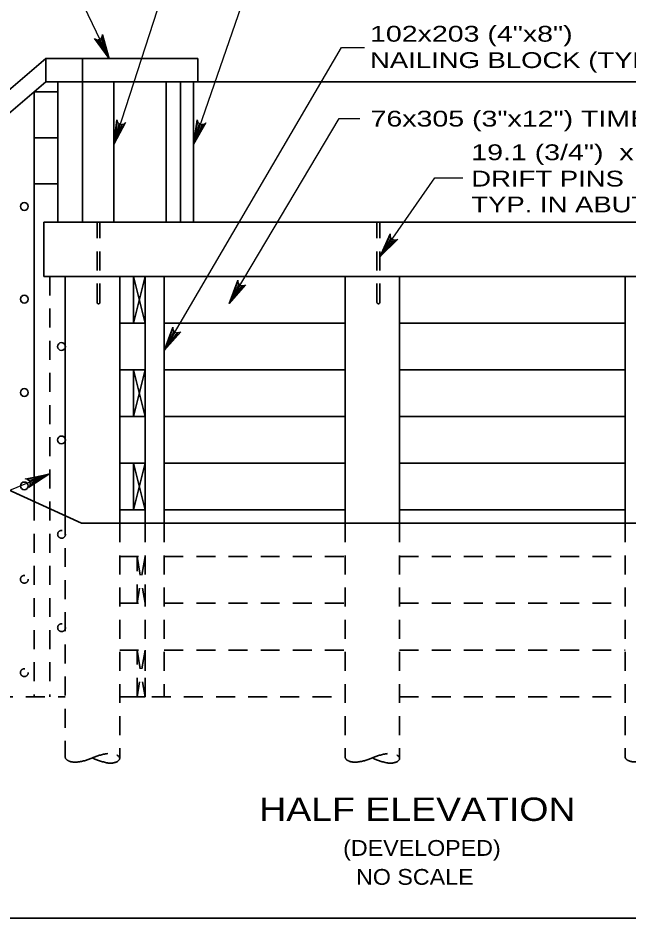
# Model space of a CAD drawing. Extents: x -6.4 to 73.1, y -66 to 0.
# Drawn here: x 7.37 to 12, y -21.25 to -14.42 of the extents above; entities that cross this region are included whole.
import ezdxf
from ezdxf.enums import TextEntityAlignment as Align

# ---------------------------------------------------------------- set-up
doc = ezdxf.new("R2010")
doc.units = 0
doc.header["$LTSCALE"] = 0.048
doc.linetypes.add('MEDIUM_DASHED', pattern=[4.5, 3, -1.5])
for name, color, linetype, lineweight in [('1', 7, 'Continuous', 13), ('4', 7, 'Continuous', 25), ('5', 7, 'Continuous', 25), ('52', 7, 'Continuous', 25)]:
    doc.layers.add(name, color=color, linetype=linetype, lineweight=lineweight)

msp = doc.modelspace()

# ---------------------------------------------------------------- hatches: boundary and pattern name
at = {"layer": '5'}
for points in [[(8.06058, -14.72783), (8.01867, -14.617), (8.00092, -14.62542)], [(8.09567, -15.38017), (8.1415, -15.27092), (8.12283, -15.26483)], [(10.1175, -16.23142), (10.193, -16.14008), (10.17692, -16.12883)], [(8.97192, -16.5865), (9.04092, -16.49008), (9.024, -16.48)], [(8.48033, -16.94342), (8.5485, -16.84642), (8.5315, -16.8365)], [(7.61, -17.87892), (7.497, -17.91467), (7.5045, -17.93292)]]:
    msp.add_hatch(color=256, dxfattribs=at).paths.add_polyline_path(points)

# ---------------------------------------------------------------- linework, layer by layer
at = {"layer": '1', "lineweight": 35}
msp.add_lwpolyline([(1.75, -21.25), (33.25, -21.25), (33.25, -0.75), (1.75, -0.75)], close=True, dxfattribs=at)
at = {"layer": '4', "lineweight": 35}
for p, q in [((7.57942, -14.72783), (5.12433, -16.82092)), ((7.57942, -14.72783), (7.57942, -14.905)), ((8.73492, -14.72783), (7.57942, -14.72783)), ((7.85875, -14.72783), (7.85875, -14.905)), ((8.73492, -14.72783), (8.73492, -14.905)), ((7.57942, -14.905), (5.12433, -16.99808)), ((8.41083, -14.905), (7.57942, -14.905)), ((7.67092, -14.905), (7.67092, -15.968)), ((7.85875, -14.905), (7.85875, -15.968)), ((8.09567, -14.905), (8.09567, -15.968)), ((8.41083, -14.905), (13.83458, -14.905)), ((8.49383, -14.905), (8.49383, -15.968)), ((8.60392, -14.905), (8.60392, -15.968)), ((8.70217, -14.905), (8.70217, -15.968)), ((7.49133, -14.98008), (7.49133, -18.08933)), ((7.49133, -14.98008), (7.63358, -14.98008)), ((7.63358, -14.97908), (7.67092, -14.97908)), ((7.49133, -15.32842), (7.67092, -15.32842)), ((7.49133, -15.67775), (7.67092, -15.67775)), ((7.56575, -15.968), (7.56575, -16.38133)), ((7.56575, -15.968), (13.83458, -15.968)), ((7.56575, -16.38133), (13.83458, -16.38133)), ((7.72817, -16.38133), (7.72817, -18.19792)), ((8.14133, -16.38133), (8.14133, -18.25408)), ((8.24625, -16.38133), (8.24625, -16.73567)), ((8.24625, -16.73567), (8.33483, -16.38133)), ((8.33483, -16.38133), (8.33483, -18.25408)), ((8.48033, -16.38133), (8.48033, -18.25408)), ((9.85417, -16.38133), (9.85417, -18.25408)), ((10.26733, -16.38133), (10.26733, -18.25408)), ((11.98008, -16.38133), (11.98008, -18.25408)), ((8.14133, -16.73567), (8.33483, -16.73567)), ((8.48033, -16.73567), (9.85417, -16.73567)), ((10.26733, -16.73567), (11.98008, -16.73567)), ((5.33375, -17.09975), (7.8505, -18.25408)), ((8.14133, -17.09), (8.33483, -17.09)), ((8.24625, -17.44433), (8.33483, -17.09)), ((8.33483, -17.44433), (8.24625, -17.09)), ((8.24625, -17.09), (8.24625, -17.44433)), ((8.33483, -17.09), (8.33483, -17.44433)), ((8.48033, -17.09), (9.85417, -17.09)), ((10.26733, -17.09), (11.98008, -17.09)), ((8.14133, -17.44433), (8.33483, -17.44433)), ((8.48033, -17.44433), (9.85417, -17.44433)), ((10.26733, -17.44433), (11.98008, -17.44433)), ((8.14133, -17.79867), (8.33483, -17.79867)), ((8.24625, -17.79867), (8.24625, -18.153)), ((8.24625, -18.153), (8.33483, -17.79867)), ((8.48033, -17.79867), (9.85417, -17.79867)), ((10.26733, -17.79867), (11.98008, -17.79867)), ((8.14133, -18.153), (8.33483, -18.153)), ((8.48033, -18.153), (9.85417, -18.153)), ((10.26733, -18.153), (11.98008, -18.153)), ((7.8505, -18.25408), (13.83458, -18.25408))]:
    msp.add_line(p, q, dxfattribs=at)
at = {"layer": '4', "linetype": 'MEDIUM_DASHED', "lineweight": 35}
for p, q in [((7.96933, -16.5785), (7.96933, -15.968)), ((7.9915, -16.5785), (7.9915, -15.968)), ((10.09533, -16.5785), (10.09533, -15.968)), ((10.1175, -16.5785), (10.1175, -15.968)), ((7.61, -16.38133), (7.61, -19.57033)), ((7.49133, -18.08933), (7.49133, -19.57033)), ((7.72817, -18.19792), (7.72817, -20.02908)), ((8.14133, -18.25408), (8.14133, -20.04)), ((8.33483, -18.25408), (8.33483, -19.57033)), ((8.48033, -18.25408), (8.48033, -19.57033)), ((9.85417, -18.25408), (9.85417, -20.02908)), ((10.26733, -18.25408), (10.26733, -20.04)), ((11.98008, -18.25408), (11.98008, -20.02683)), ((8.14133, -18.50733), (8.33483, -18.50733)), ((8.33483, -18.50733), (8.27317, -18.86167)), ((8.27317, -18.86167), (8.27317, -18.50733)), ((8.48033, -18.50733), (9.85417, -18.50733)), ((10.26733, -18.50733), (11.98008, -18.50733)), ((8.14133, -18.86167), (8.33483, -18.86167)), ((8.48033, -18.86167), (9.85417, -18.86167)), ((10.26733, -18.86167), (11.98008, -18.86167)), ((8.14133, -19.216), (8.33483, -19.216)), ((8.27317, -19.57033), (8.27317, -19.216)), ((8.27317, -19.216), (8.33483, -19.57033)), ((8.33483, -19.216), (8.27317, -19.57033)), ((8.33483, -19.57033), (8.33483, -19.216)), ((8.48033, -19.216), (9.85417, -19.216)), ((10.26733, -19.216), (11.98008, -19.216)), ((6.94125, -19.57033), (7.72817, -19.57033)), ((8.14133, -19.57033), (9.85417, -19.57033)), ((8.19092, -19.57033), (8.36808, -19.57033)), ((10.26733, -19.57033), (11.98008, -19.57033))]:
    msp.add_line(p, q, dxfattribs=at)
at = {"layer": '4', "lineweight": 35}
for points in [[(8.33483, -16.38133), (8.33483, -16.73567), (8.24625, -16.38133)], [(8.33483, -17.79867), (8.33483, -18.153), (8.24625, -17.79867)]]:
    msp.add_lwpolyline(points, dxfattribs=at)
at = {"layer": '4', "linetype": 'MEDIUM_DASHED', "lineweight": 35}
msp.add_lwpolyline([(8.27317, -18.50733), (8.33483, -18.86167), (8.33483, -18.50733)], dxfattribs=at)
at = {"layer": '4', "lineweight": 35}
for centre in [(7.41706, -15.84965), (7.41706, -16.55329), (7.69913, -16.91286), (7.41706, -17.26195), (7.69913, -17.62152), (7.41706, -17.97061)]:
    msp.add_circle(centre, 0.02953, dxfattribs=at)
at = {"layer": '4', "linetype": 'MEDIUM_DASHED', "lineweight": 35}
for centre in [(7.6997, -18.33781), (7.41706, -18.67927), (7.6997, -19.04647), (7.41706, -19.38793)]:
    msp.add_circle(centre, 0.02953, dxfattribs=at)
for centre in [(7.98048, -16.5768), (10.10646, -16.5768)]:
    msp.add_arc(centre, 0.0112, 188.67353, 351.32647, dxfattribs=at)
for centre, major_axis, start_param, end_param in [((8.13864, -20.14329), (0.29215, -0.00772), 1.8903203, 2.3561945), ((8.06818, -20.03807), (0.07318, -0.00193), 4.4555879, 8.1107827), ((10.26464, -20.14329), (0.29215, -0.00772), 1.8903203, 2.3561945), ((10.19418, -20.03807), (0.07318, -0.00193), 4.4555879, 8.1107827), ((7.80138, -20.03102), (-0.07318, 0.00193), 6.2831853, 8.1107827), ((7.73093, -19.92579), (-0.29215, 0.00772), 1.8903203, 2.3561945), ((8.1441, -19.93671), (0.29215, -0.00772), 3.9269908, 4.392865), ((9.92738, -20.03102), (-0.07318, 0.00193), 6.2831853, 8.1107827), ((9.85693, -19.92579), (-0.29215, 0.00772), 1.8903203, 2.3561945), ((10.2701, -19.93671), (0.29215, -0.00772), 3.9269908, 4.392865), ((12.05331, -20.02877), (-0.0732, 0.00193), 6.2831853, 8.1107827)]:
    msp.add_ellipse(centre, major_axis=major_axis, ratio=0.5, start_param=start_param, end_param=end_param, dxfattribs=at)
at = {"layer": '5'}
for p, q in [((8.09567, -15.38017), (8.69033, -13.55058)), ((8.06058, -14.72783), (7.82075, -14.22442)), ((8.70217, -15.38017), (9.08692, -14.26717)), ((8.48033, -16.94342), (9.82658, -14.64217)), ((9.82658, -14.64217), (10.00125, -14.64217)), ((8.97192, -16.5865), (9.80942, -15.18325)), ((9.80942, -15.18325), (9.96633, -15.18325)), ((7.61, -17.87892), (4.828, -19.02125))]:
    msp.add_line(p, q, dxfattribs=at)
for points in [[(8.06058, -14.72783), (7.94883, -14.57458), (7.964, -14.58325), (7.9785, -14.58458), (7.99067, -14.58117), (8.00108, -14.57383), (8.00917, -14.56175), (8.012, -14.5445), (8.06058, -14.72783), (8.00917, -14.56175), (8.00108, -14.57383), (8.06058, -14.72783), (7.99067, -14.58117), (7.9785, -14.58458), (8.06058, -14.72783), (7.964, -14.58325)], [(8.09567, -15.38017), (8.12008, -15.19208), (8.12508, -15.20883), (8.13467, -15.21975), (8.14592, -15.22558), (8.15842, -15.22742), (8.17258, -15.22425), (8.1865, -15.21367), (8.09567, -15.38017), (8.17258, -15.22425), (8.15842, -15.22742), (8.09567, -15.38017), (8.14592, -15.22558), (8.13467, -15.21975), (8.09567, -15.38017), (8.12508, -15.20883)], [(10.1175, -16.23142), (10.53542, -15.63225), (10.74742, -15.63225)], [(10.1175, -16.23142), (10.19525, -16.05842), (10.19525, -16.07592), (10.20125, -16.08917), (10.21033, -16.098), (10.22183, -16.10342), (10.23633, -16.1045), (10.25267, -16.09833), (10.1175, -16.23142), (10.23633, -16.1045), (10.22183, -16.10342), (10.1175, -16.23142), (10.21033, -16.098), (10.20125, -16.08917), (10.1175, -16.23142), (10.19525, -16.07592)], [(8.97192, -16.5865), (9.03742, -16.4085), (9.03858, -16.42592), (9.04558, -16.43875), (9.05517, -16.447), (9.067, -16.4515), (9.08158, -16.45158), (9.0975, -16.44433), (8.97192, -16.5865), (9.08158, -16.45158), (9.067, -16.4515), (8.97192, -16.5865), (9.05517, -16.447), (9.04558, -16.43875), (8.97192, -16.5865), (9.03858, -16.42592)], [(8.48033, -16.94342), (8.54433, -16.76483), (8.54567, -16.78225), (8.55267, -16.795), (8.56242, -16.80317), (8.57425, -16.80758), (8.58875, -16.8075), (8.60467, -16.80017), (8.48033, -16.94342), (8.58875, -16.8075), (8.57425, -16.80758), (8.48033, -16.94342), (8.56242, -16.80317), (8.55267, -16.795), (8.48033, -16.94342), (8.54567, -16.78225)], [(7.61, -17.87892), (7.45083, -17.98208), (7.46033, -17.96742), (7.46242, -17.953), (7.45967, -17.94067), (7.45292, -17.92992), (7.44133, -17.92117), (7.42425, -17.91742), (7.61, -17.87892), (7.44133, -17.92117), (7.45292, -17.92992), (7.61, -17.87892), (7.45967, -17.94067), (7.46242, -17.953), (7.61, -17.87892), (7.46033, -17.96742)]]:
    msp.add_lwpolyline(points, dxfattribs=at)
for points in [[(8.06058, -14.72783), (8.01867, -14.617), (8.00092, -14.62542)], [(8.09567, -15.38017), (8.1415, -15.27092), (8.12283, -15.26483)], [(10.1175, -16.23142), (10.193, -16.14008), (10.17692, -16.12883)], [(8.97192, -16.5865), (9.04092, -16.49008), (9.024, -16.48)], [(8.48033, -16.94342), (8.5485, -16.84642), (8.5315, -16.8365)], [(7.61, -17.87892), (7.497, -17.91467), (7.5045, -17.93292)]]:
    msp.add_lwpolyline(points, close=True, dxfattribs=at)
at = {"layer": '52'}
msp.add_lwpolyline([(8.70217, -15.38017), (8.73, -15.19258), (8.73475, -15.20942), (8.74417, -15.2205), (8.75525, -15.22658), (8.76775, -15.22867), (8.782, -15.22575), (8.79608, -15.21542), (8.70217, -15.38017), (8.782, -15.22575), (8.76775, -15.22867), (8.70217, -15.38017), (8.75525, -15.22658), (8.74417, -15.2205), (8.70217, -15.38017), (8.73475, -15.20942)], dxfattribs=at)

# ---------------------------------------------------------------- texts
at = {"layer": '5'}
for s, width, p in [('102x203 (4"x8")', 1.35, (10.04267, -14.599)), ('NAILING BLOCK (TYP.)', 1.3, (10.04267, -14.799)), ('76x305 (3"x12") TIMBER LAGGING ABUT.', 1.35, (10.04658, -15.24325)), ('19.1 (3/4")  x 508 (1\'-8")', 1.35, (10.81167, -15.49833)), ('DRIFT PINS', 1.3, (10.81167, -15.69833)), ('TYP. IN ABUTMENT PILES', 1.3, (10.81167, -15.89417))]:
    msp.add_text(s, height=0.12, dxfattribs=dict(at, width=width)).set_placement(p)
for s, height, width, p in [('HALF ELEVATION', 0.1772, 1.2, (10.40217, -20.51325)), ('(DEVELOPED)', 0.12, 1.1, (10.43696, -20.77833)), ('NO SCALE', 0.12, 1.1, (10.38296, -20.99808))]:
    msp.add_text(s, height=height, dxfattribs=dict(at, width=width)).set_placement(p, align=Align.CENTER)

doc.saveas('drawing.dxf')
